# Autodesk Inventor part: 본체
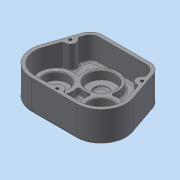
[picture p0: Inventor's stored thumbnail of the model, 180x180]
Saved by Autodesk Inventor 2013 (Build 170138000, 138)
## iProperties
Created: 2014-12
Part Number: 본체
Material: 일반
Document SubType Name: Modeling
Designer: Administrator
Density: 1 g/cm^3
Author: Administrator
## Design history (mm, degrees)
sketch "스케치1"
  geometry: L1 (-47, 36)-(47, 36); L2 (0, 0)-(-32.527, -32.527); L3 (0, 0)-(32.527, -32.527); L4 (0, 0)-(0, -73.351); L5 (-47, 36)-(-66.565, -20.803); L6 (47, 36)-(66.565, -20.803); L7 (-32.527, -68.527)-(32.527, -68.527); A1 r 46 centre (0, 0) between (-32.527, -32.527) and (32.527, -32.527); A2 r 36 centre (-32.527, -32.527) between (-66.565, -20.803) and (-32.527, -68.527); A3 r 36 centre (32.527, -32.527) between (32.527, -68.527) and (66.565, -20.803); A4 r 36 centre (32.527, -32.527) between (-0.86, -45.992) and (0, -47.954); 3 further points
  constraints: 14 end point, 9 point on circle, 4 centre point, 4 tangent, 3 coincident, 2 vertical alignment, 1 equal radius, 1 horizontal, 1 midpoint, 1 parallel, 1 point on line
  dimensions: "d0" = 94 distance of L1.start L1.end; "d2" = 92 diameter of A1; "d4" = 45 deg angle of L4 L2; "d5" = 45 deg angle of L4 L3; "d8" = 36 distance from line of point (0, 0) L1; "d9" = 36 radius of A2
extrude "돌출1" new body sketch "스케치1" distance "d13" = 44; taper "d14" = 0 deg
fillet "모깎기1" dims "d15" = 18
feature "쉘1" dims "d16" = 5
sketch "스케치12"
  geometry: L1 (0, 0)-(68.324, 0) reference; L2 (-27.675, -53.432)-(-12.291, -8.767) reference; L3 (66.689, -94.527)-(1.635, -94.527) reference; L4 (80.615, -8.767)-(95.999, -53.432) reference; A1 r 13 centre (68.324, -13) between (80.615, -8.767) and (68.324, 0) reference; A2 r 13 centre (0, -13) between (0, 0) and (-12.291, -8.767) reference; A3 r 31 centre (1.635, -63.527) between (-27.675, -53.432) and (1.635, -94.527) reference; A4 r 31 centre (66.689, -63.527) between (66.689, -94.527) and (95.999, -53.432) reference; 1 further point
extrude "돌출10" join sketch "스케치12" distance "d64" = 5; taper "d65" = 0 deg
sketch "스케치3"
  geometry: C1 r 20 at (-32.527, -32.527); C2 r 20 at (32.527, -32.527); A1 r 36 centre (-32.527, -32.527) between (-66.565, -20.803) and (-32.527, -68.527) reference; A2 r 36 centre (32.527, -32.527) between (32.527, -68.527) and (66.565, -20.803) reference; 1 further point
  constraints: 2 centre point, 2 coincident
  dimensions: "d22" = 40 diameter of C1; "d23" = 40 diameter of C2
extrude "돌출3" join sketch "스케치3" distance "d24" = 7; taper "d25" = -10 deg
sketch "스케치4"
  geometry: C1 r 18.766 at (0, 0) reference; C2 r 15 at (0, 0); 1 further point
  constraints: 1 centre point, 1 coincident
  dimensions: "d26" = 30 diameter of C2
extrude "돌출4" cut sketch "스케치4" distance "d27" = 7; taper "d28" = 0 deg
sketch "스케치5"
  geometry: C1 r 18.766 at (0, 0) reference; C2 r 15 at (0, 0); 1 further point
  constraints: 1 centre point, 1 coincident
  dimensions: "d29" = 30 diameter of C2
extrude "돌출5" cut sketch "스케치5" distance "d30" = 7; taper "d31" = 0 deg
sketch "스케치6"
  geometry: L1 (68.324, 5)-(0, 5) reference; L2 (100.726, -51.803)-(85.343, -7.138) reference; L3 (80.615, -8.767)-(95.999, -53.432) reference; A1 r 8 centre (85.862, -24) between (88.556, -16.467) and (92.623, -28.276)
  constraints: 2 point on circle, 2 point on line, 1 centre point
  dimensions: "d32" = 16 diameter of A1; "d33" = 29 distance from line of A1.centre L1; "d34" = 5 distance from line of L2 A1.centre
extrude "돌출6" join sketch "스케치6" distance "d35" = 39; taper "d36" = 0 deg
sketch "스케치7"
  geometry: L1 (68.324, 5)-(0, 5) reference; L2 (-17.019, -7.138)-(-32.403, -51.803) reference; A1 r 8 centre (-17.538, -24) between (-24.299, -28.276) and (-20.232, -16.467)
  constraints: 2 point on circle, 2 point on line, 1 centre point
  dimensions: "d37" = 16 diameter of A1; "d38" = 29 distance from line of L1 A1.centre; "d39" = 5 distance from line of L2 A1.centre
extrude "돌출7" join sketch "스케치7" distance "d40" = 39; taper "d41" = 0 deg
sketch "스케치8"
  geometry: L1 (68.324, 5)-(0, 5) reference; L2 (1.635, -99.527)-(66.689, -99.527) reference; A1 r 8 centre (34.162, -94.527) between (40.407, -99.527) and (27.917, -99.527); 1 further point
  constraints: 2 point on circle, 2 point on line, 1 centre point, 1 midpoint, 1 vertical alignment
  dimensions: "d42" = 16 diameter of A1; "d43" = 5 distance from line of L2 A1.centre
extrude "돌출8" join sketch "스케치8" distance "d44" = 39; taper "d45" = 0 deg
sketch "스케치9"
  geometry: A1 r 8 centre (51.7, 7) between (49.095, 14.564) and (54.305, -0.564) reference; 1 further point
hole "구멍1" sketch "스케치9" at (51.7, 7) diameter "d46" = 4.134; stored, may be unused: countersink angle "d50" = 90 deg, drill point angle "d52" = 118 deg; dims "d47" = 20, "d48" = 4, "d49" = 2, "d51" = 23
sketch "스케치10"
  geometry: A1 r 8 centre (-51.7, 7) between (-54.305, -0.564) and (-49.095, 14.564) reference; A2 r 8 centre (0, -63.527) between (8, -63.527) and (-8, -63.527) reference; 1 further point
hole "구멍2" sketch "스케치10" at (-51.7, 7), (0, -63.527) diameter "d53" = 4.134; stored, may be unused: countersink angle "d57" = 90 deg, drill point angle "d59" = 118 deg; dims "d54" = 20, "d55" = 4, "d56" = 2, "d58" = 23
sketch "스케치15"
  geometry: C1 r 24 at (34.162, -31); C2 r 24 at (1.635, -63.527); C3 r 24 at (66.689, -63.527); A1 r 31 centre (66.689, -63.527) between (66.689, -94.527) and (95.999, -53.432) reference; A2 r 31 centre (1.635, -63.527) between (-27.675, -53.432) and (1.635, -94.527) reference; 1 further point
  constraints: 3 centre point, 3 coincident
  dimensions: "d66" = 48 diameter of C1; "d67" = 48 diameter of C2; "d68" = 48 diameter of C3
extrude "돌출11" join sketch "스케치15" distance "d69" = 11; taper "d70" = 0 deg
sketch "스케치16"
  geometry: C1 r 20 at (34.162, -31); A1 r 24 centre (34.162, -31) between (55.273, -42.416) and (13.051, -42.416) reference
  constraints: 1 centre point, 1 coincident
  dimensions: "d71" = 40 diameter of C1
extrude "돌출12" cut sketch "스케치16" distance "d72" = 12; taper "d73" = 0 deg
sketch "스케치17"
  geometry: C1 r 17.5 at (1.635, -63.527); C2 r 17.5 at (66.689, -63.527); A1 r 24 centre (66.689, -63.527) between (45.578, -52.111) and (55.273, -42.416) reference; A2 r 24 centre (1.635, -63.527) between (13.051, -42.416) and (22.746, -52.111) reference
  constraints: 2 centre point, 2 coincident
  dimensions: "d74" = 35 diameter of C1; "d75" = 35 diameter of C2
extrude "돌출13" cut sketch "스케치17" distance "d76" = 11; taper "d77" = 0 deg
sketch "스케치18"
  geometry: C1 r 15 at (0, 0) reference; C2 r 7.75 at (0, 0); 1 further point
  constraints: 1 centre point, 1 coincident
  dimensions: "d78" = 15.5 diameter of C2
extrude "돌출14" cut sketch "스케치18" stored distance "d79" = 11; taper "d80" = 0 deg
sketch "스케치19"
  geometry: C1 r 15 at (0, 0) reference; C2 r 7.75 at (0, 0); 1 further point
  constraints: 1 centre point, 1 coincident
  dimensions: "d81" = 15.5 diameter of C2
extrude "돌출15" cut sketch "스케치19" stored distance "d82" = 11; taper "d83" = 0 deg
sketch "스케치20"
  geometry: C1 r 20 at (0, 0) reference; C2 r 10 at (0, 0)
  constraints: 1 centre point, 1 coincident
  dimensions: "d84" = 20 diameter of C2
extrude "돌출16" cut sketch "스케치20" distance "d85" = 3; taper "d86" = 0 deg
fillet "모깎기2" dims "d87" = 3
fillet "모깎기3" dims "d88" = 3
fillet "모깎기4" dims "d89" = 3
fillet "모깎기5" dims "d90" = 3
fillet "모깎기6" dims "d91" = 3
chamfer "모따기1" distance "d92" = 1; stored, may be unused: second distance "d93" = 2, angle "d94" = 45 deg
fillet "모깎기7" dims "d95" = 0.3
fillet "모깎기8" dims "d96" = 0.1
sketch "스케치21"
  geometry: L1 (-34.162, 33)-(34.162, 33) reference; L2 (34.162, 36)-(-34.162, 36) reference; 3 further points
  constraints: 1 midpoint, 1 vertical alignment, 1 other
  dimensions: "d97" = 30 distance from line of L2 point (0, 6)
feature "엠보싱1" sketch "스케치21" dims "d0" = 94, "d2" = 92, "d4" = 45 deg, "d5" = 45 deg, "d8" = 36, "d9" = 36, "d98" = 1, "d99" = 0
fillet "모깎기9" dims "d100" = 3
sketch "스케치22"
  geometry: 1 further point
fillet "모깎기10" dims "d101" = 3
node "솔리드1"
other parameters: "d6" = 72, "d7" = 72
